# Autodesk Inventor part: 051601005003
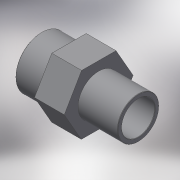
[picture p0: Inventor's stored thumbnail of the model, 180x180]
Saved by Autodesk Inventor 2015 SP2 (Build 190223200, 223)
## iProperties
Created: 2017-10
Part Number: 051601005003
Material: Generic
Description: PLASSON THR. REDUCING NIPPLE 1/2"-3/8" PVC
Document SubType Name: Modeling
Designer: KIM
Density: 1 g/cm^3
Appearance: Default
Author: KIM
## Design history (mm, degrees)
derived "051601.ipt"
feature "Solid1::051601.ipt"
tag "TaggingFeature1"
body "Solid1"
other parameters: "d0" = 39, "d2" = 24, "d13" = 0, "d14" = 0.16662, "d17" = 11, "d18" = 19.2, "d19" = 20.955, "d21" = 16.662, "d23" = 16.764, "d24" = 13.3296, "d25" = 16, "d26" = -11, "R_1" = 16.662, "C_" = 24, "lt_1" = 11, "lt_" = 16, "H_" = 39, "R_" = 20.955
